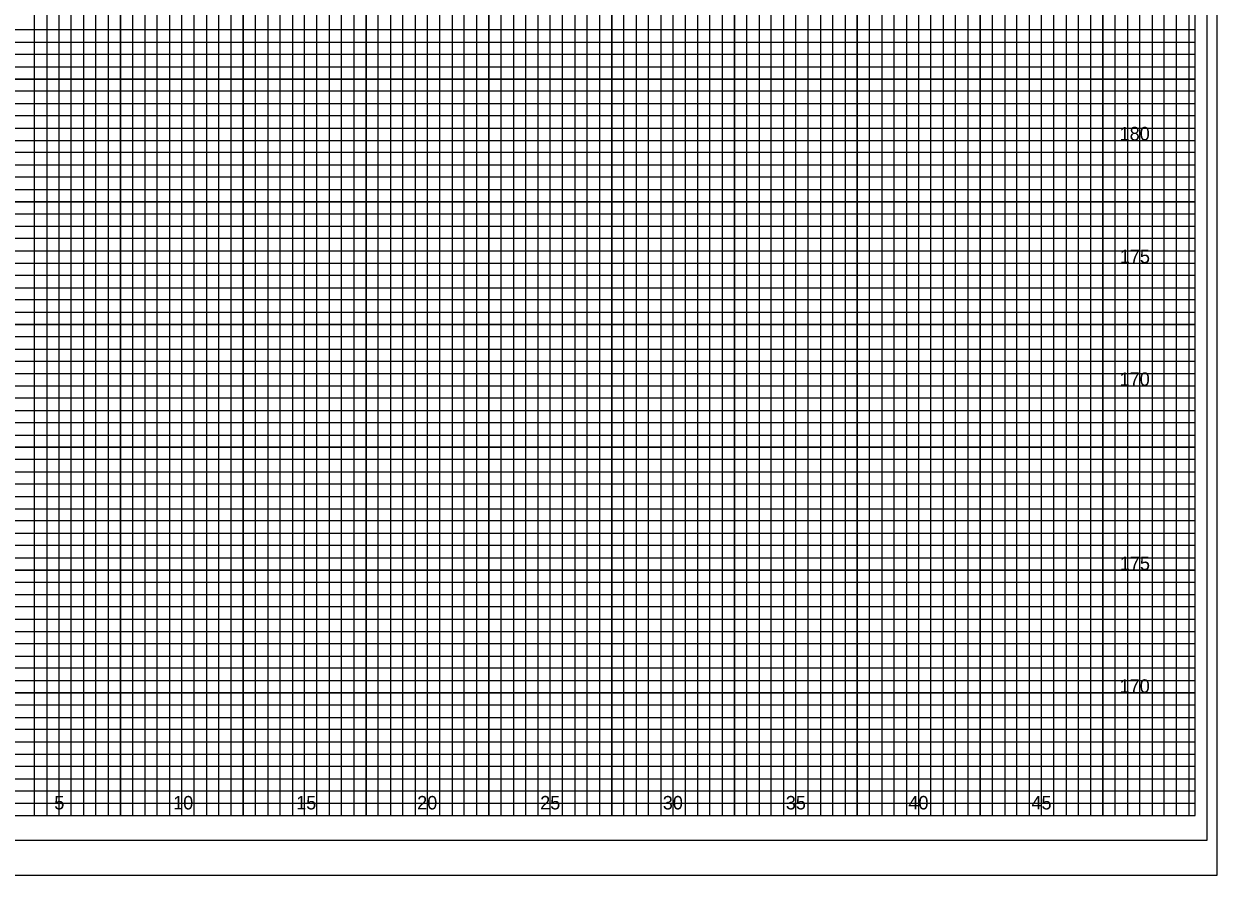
# Model space of a CAD drawing. Extents: x -4 to 103, y -2 to 209.
# Drawn here: x 54.82 to 103.4, y 68.4 to 103.07 of the extents above; entities that cross this region are included whole.
import ezdxf

# ---------------------------------------------------------------- set-up
doc = ezdxf.new("R2010")
doc.units = 0
for name, color, linetype in [('Prop XS Elevation Labels', 7, 'Continuous'), ('Prop XS Offset Labels', 7, 'Continuous'), ('Sheet Cross Section CELL', 7, 'Continuous'), ('Sheet Cross Section Grid Major CELL', 7, 'Continuous'), ('Sheet Cross Section Grid Middle CELL', 7, 'Continuous'), ('Sheet Cutting Line CELL', 7, 'Continuous'), ('Sheet DOT Grid CELL', 7, 'Continuous'), ('Sheet Plot Border Inside CELL', 7, 'Continuous'), ('Sheet Plot Border Outside CELL', 7, 'Continuous')]:
    doc.layers.add(name, color=color, linetype=linetype)

msp = doc.modelspace()

# ---------------------------------------------------------------- linework, layer by layer
at = {"layer": 'Sheet Cross Section CELL'}
msp.add_lwpolyline([(102.5, 135.825), (0, 135.825), (0, 70.825), (102.5, 70.825)], close=True, dxfattribs=at)
at = {"layer": 'Sheet Cross Section Grid Major CELL'}
for points in [[(56.25, 70.825), (56.25, 135.825)], [(58.75, 135.825), (58.75, 70.825), (61.25, 70.825), (61.25, 135.825)], [(63.75, 135.825), (63.75, 70.825), (66.25, 70.825), (66.25, 135.825)], [(68.75, 135.825), (68.75, 70.825), (71.25, 70.825), (71.25, 135.825)], [(73.75, 135.825), (73.75, 70.825), (76.25, 70.825), (76.25, 132.825)], [(88.75, 132.825), (88.75, 70.825), (91.25, 70.825), (91.25, 134.25)], [(93.75, 134.25), (93.75, 70.825), (96.25, 70.825), (96.25, 134.25)], [(98.75, 134.25), (98.75, 70.825), (101.25, 70.825), (101.25, 134.25)], [(78.75, 132.825), (78.75, 70.825), (81.25, 70.825), (81.25, 132.825)], [(83.75, 132.825), (83.75, 70.825), (86.25, 70.825), (86.25, 132.825)], [(0, 98.325), (102.5, 98.325), (102.5, 100.825), (0, 100.825)], [(0, 93.325), (102.5, 93.325), (102.5, 95.825), (0, 95.825)], [(0, 88.325), (102.5, 88.325), (102.5, 90.825), (0, 90.825)], [(0, 83.325), (102.5, 83.325), (102.5, 85.825), (0, 85.825)], [(0, 78.325), (102.5, 78.325), (102.5, 80.825), (0, 80.825)], [(0, 73.325), (102.5, 73.325), (102.5, 75.825), (0, 75.825)]]:
    msp.add_lwpolyline(points, dxfattribs=at)
at = {"layer": 'Sheet Cross Section Grid Middle CELL'}
for points in [[(54.75, 70.825), (55.25, 70.825), (55.25, 135.825)], [(55.75, 135.825), (55.75, 70.825), (56.75, 70.825), (56.75, 135.825)], [(57.25, 135.825), (57.25, 70.825), (57.75, 70.825), (57.75, 135.825)], [(58.25, 135.825), (58.25, 70.825), (59.25, 70.825), (59.25, 135.825)], [(59.75, 135.825), (59.75, 70.825), (60.25, 70.825), (60.25, 135.825)], [(60.75, 135.825), (60.75, 70.825), (61.75, 70.825), (61.75, 135.825)], [(62.25, 135.825), (62.25, 70.825), (62.75, 70.825), (62.75, 135.825)], [(63.25, 135.825), (63.25, 70.825), (64.25, 70.825), (64.25, 135.825)], [(64.75, 135.825), (64.75, 70.825), (65.25, 70.825), (65.25, 135.825)], [(65.75, 135.825), (65.75, 70.825), (66.75, 70.825), (66.75, 135.825)], [(67.25, 135.825), (67.25, 70.825), (67.75, 70.825), (67.75, 135.825)], [(68.25, 135.825), (68.25, 70.825), (69.25, 70.825), (69.25, 135.825)], [(69.75, 135.825), (69.75, 70.825), (70.25, 70.825), (70.25, 135.825)], [(70.75, 135.825), (70.75, 70.825), (71.75, 70.825), (71.75, 135.825)], [(72.25, 135.825), (72.25, 70.825), (72.75, 70.825), (72.75, 135.825)], [(73.25, 135.825), (73.25, 70.825), (74.25, 70.825), (74.25, 132.825)], [(89.75, 132.825), (89.75, 70.825), (90.25, 70.825), (90.25, 134.25)], [(90.75, 134.25), (90.75, 70.825), (91.75, 70.825), (91.75, 134.25)], [(92.25, 134.25), (92.25, 70.825), (92.75, 70.825), (92.75, 134.25)], [(93.25, 134.25), (93.25, 70.825), (94.25, 70.825), (94.25, 134.25)], [(94.75, 134.25), (94.75, 70.825), (95.25, 70.825), (95.25, 134.25)], [(95.75, 134.25), (95.75, 70.825), (96.75, 70.825), (96.75, 134.25)], [(97.25, 134.25), (97.25, 70.825), (97.75, 70.825), (97.75, 134.25)], [(98.25, 134.25), (98.25, 70.825), (99.25, 70.825), (99.25, 134.25)], [(99.75, 134.25), (99.75, 70.825), (100.25, 70.825), (100.25, 134.25)], [(100.25, 134.25), (100.75, 134.25), (100.75, 70.825), (101.75, 70.825), (101.75, 134.25), (102.25, 134.25), (102.25, 70.825)], [(74.75, 132.825), (74.75, 70.825), (75.25, 70.825), (75.25, 132.825)], [(75.75, 132.825), (75.75, 70.825), (76.75, 70.825), (76.75, 132.825)], [(77.25, 132.825), (77.25, 70.825), (77.75, 70.825), (77.75, 132.825)], [(78.25, 132.825), (78.25, 70.825), (79.25, 70.825), (79.25, 132.825)], [(79.75, 132.825), (79.75, 70.825), (80.25, 70.825), (80.25, 132.825)], [(80.75, 132.825), (80.75, 70.825), (81.75, 70.825), (81.75, 132.825)], [(82.25, 132.825), (82.25, 70.825), (82.75, 70.825), (82.75, 132.825)], [(83.25, 132.825), (83.25, 70.825), (84.25, 70.825), (84.25, 132.825)], [(84.75, 132.825), (84.75, 70.825), (85.25, 70.825), (85.25, 132.825)], [(85.75, 132.825), (85.75, 70.825), (86.75, 70.825), (86.75, 132.825)], [(87.25, 132.825), (87.25, 70.825), (87.75, 70.825), (87.75, 132.825)], [(88.25, 132.825), (88.25, 70.825), (89.25, 70.825), (89.25, 132.825)], [(0, 102.325), (102.5, 102.325), (102.5, 102.825), (0, 102.825)], [(0, 101.325), (102.5, 101.325), (102.5, 101.825), (0, 101.825)], [(0, 99.825), (102.5, 99.825), (102.5, 100.325), (0, 100.325)], [(0, 98.825), (102.5, 98.825), (102.5, 99.325), (0, 99.325)], [(0, 97.325), (102.5, 97.325), (102.5, 97.825), (0, 97.825)], [(0, 96.325), (102.5, 96.325), (102.5, 96.825), (0, 96.825)], [(0, 94.825), (102.5, 94.825), (102.5, 95.325), (0, 95.325)], [(0, 93.825), (102.5, 93.825), (102.5, 94.325), (0, 94.325)], [(0, 92.325), (102.5, 92.325), (102.5, 92.825), (0, 92.825)], [(0, 91.325), (102.5, 91.325), (102.5, 91.825), (0, 91.825)], [(0, 89.825), (102.5, 89.825), (102.5, 90.325), (0, 90.325)], [(0, 88.825), (102.5, 88.825), (102.5, 89.325), (0, 89.325)], [(0, 87.325), (102.5, 87.325), (102.5, 87.825), (0, 87.825)], [(0, 86.325), (102.5, 86.325), (102.5, 86.825), (0, 86.825)], [(0, 84.825), (102.5, 84.825), (102.5, 85.325), (0, 85.325)], [(0, 83.825), (102.5, 83.825), (102.5, 84.325), (0, 84.325)], [(0, 82.325), (102.5, 82.325), (102.5, 82.825), (0, 82.825)], [(0, 81.325), (102.5, 81.325), (102.5, 81.825), (0, 81.825)], [(0, 79.825), (102.5, 79.825), (102.5, 80.325), (0, 80.325)], [(0, 78.825), (102.5, 78.825), (102.5, 79.325), (0, 79.325)], [(0, 77.325), (102.5, 77.325), (102.5, 77.825), (0, 77.825)], [(0, 76.325), (102.5, 76.325), (102.5, 76.825), (0, 76.825)], [(0, 74.825), (102.5, 74.825), (102.5, 75.325), (0, 75.325)], [(0, 73.825), (102.5, 73.825), (102.5, 74.325), (0, 74.325)], [(0, 72.325), (102.5, 72.325), (102.5, 72.825), (0, 72.825)], [(0, 71.325), (102.5, 71.325), (102.5, 71.825), (0, 71.825)]]:
    msp.add_lwpolyline(points, dxfattribs=at)
at = {"layer": 'Sheet Cutting Line CELL'}
msp.add_line((-3.5, 68.4), (103.4, 68.4), dxfattribs=at)
at = {"layer": 'Sheet DOT Grid CELL'}
for p, q in [((56.25, 70.825), (56.25, 135.825)), ((58.75, 70.825), (58.75, 135.825)), ((61.25, 70.825), (61.25, 135.825)), ((63.75, 70.825), (63.75, 135.825)), ((66.25, 70.825), (66.25, 135.825)), ((68.75, 70.825), (68.75, 135.825)), ((71.25, 70.825), (71.25, 135.825)), ((73.75, 70.825), (73.75, 135.825)), ((91.25, 70.825), (91.25, 134.25)), ((93.75, 70.825), (93.75, 134.25)), ((96.25, 70.825), (96.25, 134.25)), ((98.75, 70.825), (98.75, 134.25)), ((101.25, 70.825), (101.25, 134.25)), ((76.25, 70.825), (76.25, 132.825)), ((78.75, 70.825), (78.75, 132.825)), ((81.25, 70.825), (81.25, 132.825)), ((83.75, 70.825), (83.75, 132.825)), ((86.25, 70.825), (86.25, 132.825)), ((88.75, 70.825), (88.75, 132.825)), ((0, 100.825), (102.5, 100.825)), ((0, 98.325), (102.5, 98.325)), ((0, 95.825), (102.5, 95.825)), ((0, 93.325), (102.5, 93.325)), ((0, 90.825), (102.5, 90.825)), ((0, 88.325), (102.5, 88.325)), ((0, 85.825), (102.5, 85.825)), ((0, 83.325), (102.5, 83.325)), ((0, 80.825), (102.5, 80.825)), ((0, 78.325), (102.5, 78.325)), ((0, 75.825), (102.5, 75.825)), ((0, 73.325), (102.5, 73.325))]:
    msp.add_line(p, q, dxfattribs=at)
at = {"layer": 'Sheet Plot Border Inside CELL'}
msp.add_lwpolyline([(103, 136.825), (-2.8, 136.825), (-2.8, 69.825), (103, 69.825)], close=True, dxfattribs=at)
at = {"layer": 'Sheet Plot Border Outside CELL'}
msp.add_lwpolyline([(103.4, 138.225), (-3.5, 138.225), (-3.5, 68.4), (103.4, 68.4)], close=True, dxfattribs=at)

# ---------------------------------------------------------------- texts
at = {"layer": 'Prop XS Elevation Labels'}
for s, p in [('180', (99.42958, 98.325)), ('175', (99.43825, 93.325)), ('170', (99.42958, 88.325)), ('175', (99.43825, 80.825)), ('170', (99.42958, 75.825))]:
    msp.add_text(s, height=0.55, dxfattribs=at).set_placement(p)
at = {"layer": 'Prop XS Offset Labels'}
for s, p in [('5', (56.05742, 71.075)), ('10', (60.89708, 71.075)), ('15', (65.90575, 71.075)), ('20', (70.83125, 71.075)), ('25', (75.83992, 71.075)), ('30', (80.83125, 71.075)), ('35', (85.83992, 71.075)), ('40', (90.83125, 71.075)), ('45', (95.83992, 71.075))]:
    msp.add_text(s, height=0.55, dxfattribs=at).set_placement(p)

doc.saveas('drawing.dxf')
